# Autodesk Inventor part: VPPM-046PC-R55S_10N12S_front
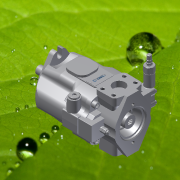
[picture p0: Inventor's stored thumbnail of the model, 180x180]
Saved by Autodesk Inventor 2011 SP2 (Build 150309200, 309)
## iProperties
Created: 2013-12
Part Number: VPPM-046PC-R55S_10N12S_front
Document SubType Name: Modeling
Designer: dorohin
Density: 1 g/cm^3
Author: dorohin
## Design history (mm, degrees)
derived "VPPM-046PC-R55S_10N12S_front.iam"
node "Твердое тело1"
node "48415601-R.ipt:1"
node "23387120.ipt:1"
sketch "42136800.ipt:1"
sketch "42136750.ipt:1"
sketch "42136800.ipt:2"
sketch "42136750.ipt:2"
sketch "06870000.ipt:1"
sketch "0530049.ipt:1"
sketch "0530049.ipt:2"
sketch "0530049.ipt:3"
sketch "0530049.ipt:4"
sketch "0551527.ipt:1"
sketch "0570181.ipt:1"
sketch "0770325.ipt:1"
sketch "0530528_.ipt:1"
sketch "0770325.ipt:2"
sketch "36740210.ipt:1"
sketch "35921470.ipt:1"
sketch "35921470.ipt:2"
sketch "35921470.ipt:3"
sketch "35921470.ipt:4"
node "47554530.ipt:1"
node "44907910.ipt:1"
sketch "42795010.ipt:1"
node "39967000.ipt:1"
node "40810000.ipt:1"
sketch "0571495_.ipt:1"
sketch "3001200200-00.ipt:1"
